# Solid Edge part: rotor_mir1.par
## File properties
Author: Argu
Template: Iso Part.par
Last saved by: Argu
Revision: 6
Application: Solid Edge
Accuracy: 0,990
Username: Argu
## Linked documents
rotor.par
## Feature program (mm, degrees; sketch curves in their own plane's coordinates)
part copy "CopiedPart_1"
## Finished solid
Body 1: solid body, 33 faces, 89 edges, 60 vertices.
  Faces by surface: spline 12, sphere 7, plane 5, cylinder 4, torus 4, cone 1
  Edges by curve: circle 56, curve on surface 18, spline 12, intersection 3
Bounding box of the edges (mm; curved faces can reach further): 397.908 x 54.298 x 345.000, from (-198.9538, -25, -115.5) to (198.9538, 29.2984, 229.5).
Cylindrical faces by radius (mm): R5 x4
Conical faces (half-angle, radius in mm at the cone's reference point): 3.9948 deg R17.975 x1
Toroidal faces (ring radius, tube radius in mm): R-369.3093 r370.8093 x3, R-273.2344 r291.9187 x1
Spherical faces by radius (mm): R1.0085 x3, R1.5 x3, R15.1202 x1
Planar faces by outward normal: -y 2, -z 1, oblique 2
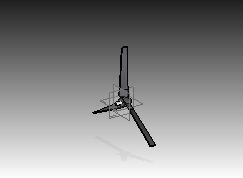
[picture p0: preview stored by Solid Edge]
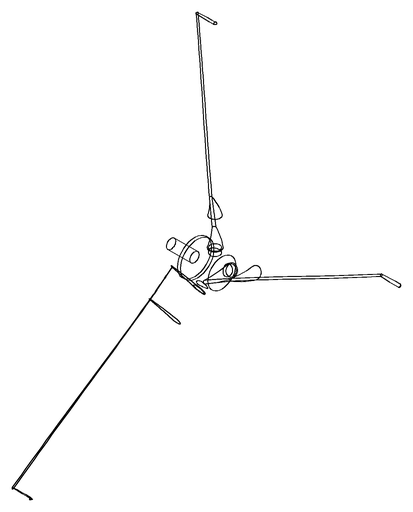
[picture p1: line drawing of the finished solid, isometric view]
